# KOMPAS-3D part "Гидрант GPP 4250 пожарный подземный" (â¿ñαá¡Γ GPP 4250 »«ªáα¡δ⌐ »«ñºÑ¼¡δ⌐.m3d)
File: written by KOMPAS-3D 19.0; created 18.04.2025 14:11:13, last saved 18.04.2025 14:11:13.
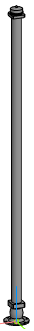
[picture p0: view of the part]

Document properties: Полное имя файла: E:\Dendor Работа Сачек\3D для проекитирвщиков\11.1 Тип GPP. Гидрант пожарный подземный\stp_Тип GPP. 750-6000 Гидрант пожарный подземный\Гидрант GPP 4250 пожарный подземный.m3d

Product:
- Part/product: Гидрант GPP 4250 пожарный подземный

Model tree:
1. Операция без истории:1  (labels: Гидрант GPP 4250 пожарный подземный)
